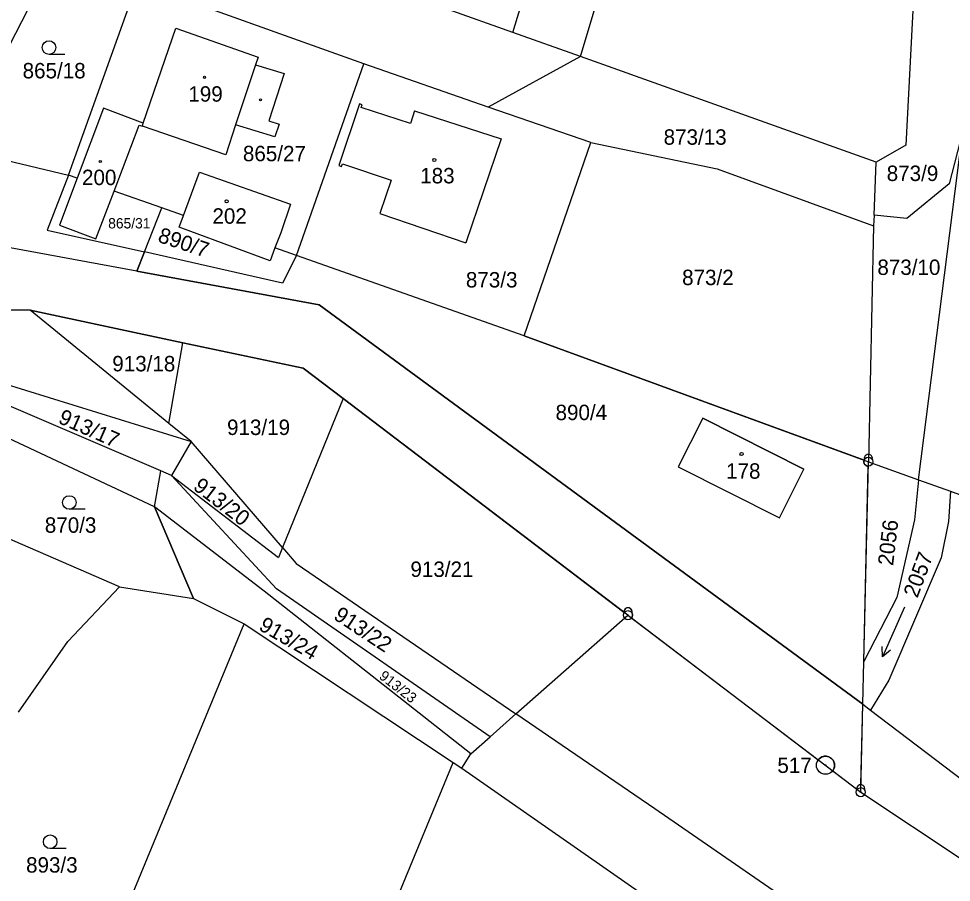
# Model space of a CAD drawing. Extents: x -801826 to -800592, y -1032871 to -1031813.
# Drawn here: x -800933.1 to -800830.2, y -1032553.2 to -1032457.9 of the extents above; entities that cross this region are included whole.
import ezdxf

# ---------------------------------------------------------------- set-up
doc = ezdxf.new("R2010")
doc.units = 0
for name, color, linetype in [('Vrstva 1', 7, 'Continuous'), ('Vrstva 17', 7, 'Continuous'), ('Vrstva 18', 7, 'Continuous'), ('Vrstva 19', 7, 'Continuous'), ('Vrstva 24', 7, 'Continuous'), ('Vrstva 25', 7, 'Continuous'), ('Vrstva 4', 7, 'Continuous')]:
    doc.layers.add(name, color=color, linetype=linetype)

msp = doc.modelspace()

# ---------------------------------------------------------------- linework, layer by layer
at = {"layer": 'Vrstva 1'}
for p, q in [((-800871.14, -1032462.11), (-800862.65, -1032433.45)), ((-800833.28, -1032433.06), (-800835.24, -1032471.87)), ((-800938.09, -1032468.54), (-800928.9, -1032450.72)), ((-800927.61, -1032475.17), (-800920.01, -1032453.97)), ((-800895.05, -1032462.91), (-800920.01, -1032453.97)), ((-800878.62, -1032459.44), (-800885.84, -1032456.88)), ((-800919.37, -1032469.46), (-800915.79, -1032458.97)), ((-800915.79, -1032458.97), (-800906.71, -1032462.16)), ((-800871.14, -1032462.11), (-800878.62, -1032459.44)), ((-800906.71, -1032462.16), (-800906.99, -1032463.02)), ((-800871.14, -1032462.11), (-800881.32, -1032467.7)), ((-800838.52, -1032473.76), (-800871.14, -1032462.11)), ((-800906.99, -1032463.02), (-800903.81, -1032463.99)), ((-800902.48, -1032484.05), (-800895.05, -1032462.91)), ((-800881.32, -1032467.7), (-800895.05, -1032462.91)), ((-800903.81, -1032463.99), (-800905.51, -1032469.2)), ((-800923.74, -1032467.81), (-800926.66, -1032475.51)), ((-800919.37, -1032469.46), (-800923.74, -1032467.81)), ((-800895.53, -1032467.33), (-800897.78, -1032474.13)), ((-800895.24, -1032467.42), (-800895.53, -1032467.33)), ((-800895.33, -1032467.71), (-800895.24, -1032467.42)), ((-800889.89, -1032469.47), (-800895.33, -1032467.71)), ((-800870.01, -1032471.6), (-800881.32, -1032467.7)), ((-800889.44, -1032468.09), (-800889.89, -1032469.47)), ((-800889.44, -1032468.09), (-800879.89, -1032471.19)), ((-800922.59, -1032476.94), (-800919.82, -1032469.67)), ((-800919.82, -1032469.67), (-800919.47, -1032469.78)), ((-800919.47, -1032469.78), (-800919.37, -1032469.46)), ((-800910.28, -1032472.93), (-800919.47, -1032469.78)), ((-800909.19, -1032469.64), (-800910.28, -1032472.93)), ((-800904.86, -1032470.97), (-800909.19, -1032469.64)), ((-800905.51, -1032469.2), (-800904.38, -1032469.55)), ((-800904.38, -1032469.55), (-800904.86, -1032470.97)), ((-800948.73, -1032470.17), (-800927.61, -1032475.17)), ((-800833.85, -1032508.78), (-800828.95, -1032470.31)), ((-800828.95, -1032470.31), (-800830.46, -1032476.14)), ((-800879.89, -1032471.19), (-800883.78, -1032482.66)), ((-800877.34, -1032492.92), (-800870.01, -1032471.6)), ((-800870.01, -1032471.6), (-800856.05, -1032474.47)), ((-800835.24, -1032471.87), (-800838.52, -1032473.76)), ((-800897.49, -1032474.23), (-800897.4, -1032473.94)), ((-800897.4, -1032473.94), (-800892.04, -1032475.75)), ((-800838.75, -1032479.59), (-800838.52, -1032473.76)), ((-800914.95, -1032479.64), (-800913.18, -1032474.86)), ((-800913.18, -1032474.86), (-800903.12, -1032478.4)), ((-800897.78, -1032474.13), (-800897.49, -1032474.23)), ((-800856.05, -1032474.47), (-800838.8, -1032480.76)), ((-800927.61, -1032475.17), (-800929.97, -1032481.24)), ((-800926.66, -1032475.51), (-800928.63, -1032480.7)), ((-800926.66, -1032475.51), (-800927.61, -1032475.17)), ((-800892.04, -1032475.75), (-800893.29, -1032479.43)), ((-800924.61, -1032482.2), (-800922.59, -1032476.94)), ((-800917.33, -1032478.8), (-800922.59, -1032476.94)), ((-800830.46, -1032476.14), (-800835.15, -1032479.96)), ((-800919.24, -1032483.65), (-800917.33, -1032478.8)), ((-800914.95, -1032479.64), (-800917.33, -1032478.8)), ((-800903.12, -1032478.4), (-800904.21, -1032481.55)), ((-800915.42, -1032480.93), (-800914.95, -1032479.64)), ((-800893.29, -1032479.43), (-800883.78, -1032482.66)), ((-800838.75, -1032479.59), (-800838.8, -1032480.76)), ((-800835.15, -1032479.96), (-800838.75, -1032479.59)), ((-800929.97, -1032481.24), (-800919.24, -1032483.65)), ((-800928.63, -1032480.7), (-800924.61, -1032482.2)), ((-800914.12, -1032481.41), (-800915.42, -1032480.93)), ((-800838.8, -1032480.76), (-800839.38, -1032506.79)), ((-800920.07, -1032485.78), (-800941.77, -1032481.76)), ((-800920.07, -1032485.78), (-800941.77, -1032481.76)), ((-800905.38, -1032484.65), (-800914.12, -1032481.41)), ((-800904.21, -1032481.55), (-800904.84, -1032483.2)), ((-800904.84, -1032483.2), (-800905.38, -1032484.65)), ((-800902.48, -1032484.05), (-800904.84, -1032483.2)), ((-800920.07, -1032485.78), (-800919.24, -1032483.65)), ((-800919.24, -1032483.65), (-800920.07, -1032485.78)), ((-800904.01, -1032487.08), (-800919.24, -1032483.65)), ((-800904.01, -1032487.08), (-800919.24, -1032483.65)), ((-800902.48, -1032484.05), (-800904.01, -1032487.08)), ((-800902.48, -1032484.05), (-800904.01, -1032487.08)), ((-800877.34, -1032492.92), (-800902.48, -1032484.05)), ((-800877.34, -1032492.92), (-800902.48, -1032484.05)), ((-800899.96, -1032489.5), (-800920.07, -1032485.78)), ((-800920.07, -1032485.78), (-800899.96, -1032489.5)), ((-800899.96, -1032489.5), (-800920.07, -1032485.78)), ((-800931.84, -1032490.09), (-800957.47, -1032489.74)), ((-800931.84, -1032490.09), (-800957.47, -1032489.74)), ((-800957.47, -1032489.74), (-800931.84, -1032490.09)), ((-800914.99, -1032493.66), (-800931.84, -1032490.09)), ((-800916.54, -1032502.56), (-800931.84, -1032490.09)), ((-800916.54, -1032502.56), (-800931.84, -1032490.09)), ((-800931.84, -1032490.09), (-800914.99, -1032493.66)), ((-800839.99, -1032533.54), (-800899.96, -1032489.5)), ((-800899.96, -1032489.5), (-800839.99, -1032533.54)), ((-800839.99, -1032533.54), (-800899.96, -1032489.5)), ((-800877.34, -1032492.92), (-800839.38, -1032506.79)), ((-800839.85, -1032506.62), (-800877.34, -1032492.92)), ((-800916.54, -1032502.56), (-800914.99, -1032493.66)), ((-800901.74, -1032496.47), (-800914.99, -1032493.66)), ((-800914.99, -1032493.66), (-800901.74, -1032496.47)), ((-800897.32, -1032499.83), (-800901.74, -1032496.47)), ((-800901.74, -1032496.47), (-800897.32, -1032499.83)), ((-800934.97, -1032498.07), (-800914.08, -1032504.56)), ((-800934.97, -1032498.07), (-800914.08, -1032504.56)), ((-800917.44, -1032507.8), (-800935.72, -1032499.98)), ((-800897.32, -1032499.83), (-800904.03, -1032516.26)), ((-800865.9, -1032523.71), (-800897.32, -1032499.83)), ((-800897.32, -1032499.83), (-800866.35, -1032523.37)), ((-800918.13, -1032511.75), (-800938.81, -1032502.08)), ((-800914.08, -1032504.56), (-800916.54, -1032502.56)), ((-800914.08, -1032504.56), (-800916.54, -1032502.56)), ((-800857.66, -1032501.99), (-800860.36, -1032507.35)), ((-800857.66, -1032501.99), (-800860.36, -1032507.35)), ((-800857.66, -1032501.99), (-800846.5, -1032507.61)), ((-800846.5, -1032507.61), (-800857.66, -1032501.99)), ((-800914.08, -1032504.56), (-800916.27, -1032508.3)), ((-800904.03, -1032516.26), (-800914.08, -1032504.56)), ((-800839.88, -1032528.82), (-800839.38, -1032506.79)), ((-800839.38, -1032506.79), (-800833.85, -1032508.78)), ((-800918.13, -1032511.75), (-800917.44, -1032507.8)), ((-800916.27, -1032508.3), (-800917.44, -1032507.8)), ((-800860.36, -1032507.35), (-800849.2, -1032512.97)), ((-800860.36, -1032507.35), (-800849.2, -1032512.97)), ((-800849.2, -1032512.97), (-800846.5, -1032507.61)), ((-800849.2, -1032512.97), (-800846.5, -1032507.61)), ((-800839.88, -1032528.82), (-800839.39, -1032507.29)), ((-800904.66, -1032520.81), (-800916.27, -1032508.3)), ((-800916.27, -1032508.3), (-800904.47, -1032517.34)), ((-800833.85, -1032508.78), (-800834.3, -1032513.2)), ((-800833.85, -1032508.78), (-800830.33, -1032510.05)), ((-800830.33, -1032510.05), (-800830.54, -1032513.39)), ((-800830.33, -1032510.05), (-800829.05, -1032510.51)), ((-800913.84, -1032521.88), (-800918.13, -1032511.75)), ((-800906.03, -1032521.07), (-800918.13, -1032511.75)), ((-800918.13, -1032511.75), (-800913.84, -1032521.88)), ((-800906.03, -1032521.07), (-800918.13, -1032511.75)), ((-800834.3, -1032513.2), (-800836.24, -1032521.77)), ((-800830.54, -1032513.39), (-800831.37, -1032517.37)), ((-800921.99, -1032520.58), (-800935.54, -1032514.69)), ((-800904.03, -1032516.26), (-800904.47, -1032517.34)), ((-800904.03, -1032516.26), (-800902.51, -1032518.02)), ((-800902.51, -1032518.02), (-800878.26, -1032534.6)), ((-800831.37, -1032517.37), (-800837.14, -1032530.89)), ((-800927.7, -1032526.63), (-800921.99, -1032520.58)), ((-800921.99, -1032520.58), (-800913.84, -1032521.88)), ((-800883.25, -1032539), (-800906.03, -1032521.07)), ((-800883.25, -1032539), (-800906.03, -1032521.07)), ((-800881.1, -1032537.11), (-800904.66, -1032520.81)), ((-800913.84, -1032521.88), (-800908.24, -1032524.68)), ((-800913.84, -1032521.88), (-800908.24, -1032524.68)), ((-800836.24, -1032521.77), (-800839.88, -1032528.82)), ((-800878.26, -1032534.6), (-800865.9, -1032523.71)), ((-800865.9, -1032523.71), (-800840.22, -1032543.23)), ((-800865.5, -1032524.01), (-800844.92, -1032539.66)), ((-800932.59, -1032583.57), (-800908.24, -1032524.68)), ((-800908.24, -1032524.68), (-800885.17, -1032539.97)), ((-800908.24, -1032524.68), (-800885.17, -1032539.97)), ((-800933.15, -1032534.42), (-800927.7, -1032526.63)), ((-800839.99, -1032533.54), (-800839.88, -1032528.82)), ((-800839.99, -1032533.54), (-800839.88, -1032528.82)), ((-800837.14, -1032530.89), (-800839.16, -1032534.17)), ((-800840.22, -1032543.23), (-800839.99, -1032533.54)), ((-800840.2, -1032542.41), (-800839.99, -1032533.54)), ((-800839.99, -1032533.54), (-800839.16, -1032534.17)), ((-800881.1, -1032537.11), (-800878.26, -1032534.6)), ((-800862.95, -1032545.07), (-800878.26, -1032534.6)), ((-800839.16, -1032534.17), (-800815.65, -1032552.08)), ((-800883.25, -1032539), (-800881.1, -1032537.11)), ((-800884.24, -1032540.59), (-800883.25, -1032539)), ((-800884.24, -1032540.59), (-800883.25, -1032539)), ((-800906.01, -1032590.17), (-800885.17, -1032539.97)), ((-800885.17, -1032539.97), (-800884.24, -1032540.59)), ((-800885.17, -1032539.97), (-800884.24, -1032540.59)), ((-800884.24, -1032540.59), (-800864.66, -1032554.23)), ((-800843.32, -1032540.88), (-800840.67, -1032542.89)), ((-800840.22, -1032543.23), (-800828.93, -1032550.72)), ((-800834.81, -1032564.44), (-800862.95, -1032545.07))]:
    msp.add_line(p, q, dxfattribs=at)
for centre, radius, start, end in [((-800839.38, -1032506.79), 0.5, 159.9285, 268.6998), ((-800865.9, -1032523.34), 0.45, 344.4473, 183.9003), ((-800865.9, -1032523.71), 0.5, 322.7606, 30.4447), ((-800844.11, -1032540.26), 1, 322.1654, 143.3559), ((-800840.22, -1032542.86), 0.45, 87.1679, 183.8943)]:
    msp.add_arc(centre, radius, start, end, dxfattribs=at)
at = {"layer": 'Vrstva 24'}
for centre, radius in [((-800839.38, -1032506.79), 0.5), ((-800839.38, -1032506.79), 0.0364), ((-800865.9, -1032523.71), 0.5), ((-800865.9, -1032523.71), 0.0364), ((-800844.11, -1032540.26), 1), ((-800844.11, -1032540.26), 0.0439), ((-800840.22, -1032543.23), 0.5), ((-800840.22, -1032543.23), 0.0364)]:
    msp.add_circle(centre, radius, dxfattribs=at)
for centre in [(-800839.38, -1032506.42), (-800865.9, -1032523.34), (-800840.22, -1032542.86)]:
    msp.add_arc(centre, 0.45, 344.4473, 196.3778, dxfattribs=at)
at = {"layer": 'Vrstva 25'}
for p, q in [((-800928.02, -1032461.86), (-800929.77, -1032461.86)), ((-800925.78, -1032512.03), (-800927.53, -1032512.03)), ((-800835.39, -1032522.81), (-800837.81, -1032528.29)), ((-800927.89, -1032549.45), (-800929.64, -1032549.45))]:
    msp.add_line(p, q, dxfattribs=at)
msp.add_lwpolyline([(-800836.95, -1032527.58), (-800837.81, -1032528.29), (-800837.86, -1032527.18)], dxfattribs=at)
for centre, radius in [((-800929.77, -1032461.11), 0.75), ((-800912.62, -1032464.39), 0.117), ((-800906.43, -1032466.87), 0.117), ((-800924.11, -1032473.68), 0.117), ((-800887.27, -1032473.51), 0.175), ((-800910.18, -1032478.07), 0.175), ((-800853.37, -1032505.94), 0.175), ((-800927.53, -1032511.28), 0.75), ((-800929.64, -1032548.7), 0.75)]:
    msp.add_circle(centre, radius, dxfattribs=at)
at = {"layer": 'Vrstva 4'}
for p, q in [((-800878.62, -1032459.44), (-800873.76, -1032443.91)), ((-800906.99, -1032463.02), (-800909.19, -1032469.64))]:
    msp.add_line(p, q, dxfattribs=at)

# ---------------------------------------------------------------- texts
at = {"layer": 'Vrstva 17'}
msp.add_text('517', height=1.7, dxfattribs=at).set_placement((-800849.42, -1032541.11))
at = {"layer": 'Vrstva 18'}
for s, height, p in [('865/18', 1.7, (-800932.68, -1032464.51)), ('873/13', 1.7, (-800861.97, -1032471.83)), ('865/27', 1.7, (-800908.38, -1032473.65)), ('873/9', 1.7, (-800837.36, -1032475.83)), ('865/31', 1.14, (-800923.24, -1032481.06)), ('873/10', 1.7, (-800838.39, -1032486.19)), ('873/3', 1.7, (-800883.78, -1032487.57)), ('873/2', 1.7, (-800859.93, -1032487.31)), ('913/18', 1.7, (-800922.79, -1032496.82)), ('890/4', 1.7, (-800873.89, -1032502.2)), ('913/19', 1.7, (-800910.13, -1032503.84)), ('870/3', 1.7, (-800930.23, -1032514.62)), ('913/21', 1.7, (-800889.9, -1032519.49)), ('893/3', 1.7, (-800932.3, -1032552.1))]:
    msp.add_text(s, height=height, dxfattribs=at).set_placement(p)
for s, height, rotation, p in [('890/7', 1.7, 341.5536, (-800917.87, -1032482.51)), ('913/17', 1.7, 336.1612, (-800928.86, -1032502.47)), ('913/20', 1.7, 322.5238, (-800913.98, -1032509.75)), ('2056', 1.7, 83.308, (-800836.66, -1032518.31)), ('2057', 1.7, 69.4998, (-800833.98, -1032521.9)), ('913/22', 1.7, 326.5446, (-800898.49, -1032524.06)), ('913/24', 1.7, 330.1218, (-800906.74, -1032525.26)), ('913/23', 1.14, 321.9771, (-800893.45, -1032530.61))]:
    msp.add_text(s, height=height, rotation=rotation, dxfattribs=at).set_placement(p)
at = {"layer": 'Vrstva 19'}
for s, p in [('199', (-800914.4, -1032467.08)), ('200', (-800926.13, -1032476.28)), ('183', (-800888.82, -1032476.09)), ('202', (-800911.74, -1032480.54)), ('178', (-800855.08, -1032508.66))]:
    msp.add_text(s, height=1.7, dxfattribs=at).set_placement(p)

doc.saveas('drawing.dxf')
